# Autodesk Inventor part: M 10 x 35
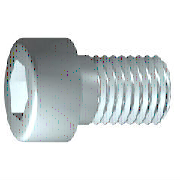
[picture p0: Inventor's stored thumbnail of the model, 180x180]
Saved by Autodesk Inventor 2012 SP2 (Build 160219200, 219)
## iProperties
IsCustomPart: 0
Created: 2009-02
Part Number: M 10 x 35
Material: 강, 연강
Description: 6각머리 태핑 나사
Document SubType Name: Modeling
Standard: KS B 1003
Designer: KYOUNG IL JANG
Standards Organization: KS
Language: ko-KR
Size Designation: M 10 x 35
Categories: <MemberInstance><Categories><Category DisplayName="조임쇠" InternalName="e4da775c-781d-43d5-af7c-5136215cf5a6" Mnemonic="FSTN"><Category DisplayName="볼트" InternalN
Density: 1 g/cm^3
Author: KYOUNG IL JANG
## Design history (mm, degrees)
workplane "Work Plane1"
fillet "Fillet2" dims "d30" = 0.1 (= R)
revolve "본체" stored, may be unused: angle "d10" = 90 deg
sketch "스케치2"
  geometry: L1 (0, -11.2)-(0, 11.2) reference; L2 (-11.2, 0)-(11.2, 0) reference; L3 (4.619, 0)-(2.309, -4); L4 (2.309, -4)-(-2.309, -4); L5 (-2.309, -4)-(-4.619, 0); L6 (-4.619, 0)-(-2.309, 4); L7 (-2.309, 4)-(2.309, 4); L8 (2.309, 4)-(4.619, 0); 2 further points
  constraints: 12 end point, 1 coincident, 1 horizontal alignment, 1 point on line, 12 other
extrude "슬롯" join sketch "스케치2" stored distance "d11" = 10; taper "d12" = 0 deg
body "Solid1"
fillet "모깎기1" dims "d17" = 1 (= RR)
feature "스레드" dims "d13" = 31.25 (= GEL), "d14" = 0
chamfer "모따기1" distance "d15" = 0.92018 (= -0.5 x SPD + 0.5 x GD); stored, may be unused: second distance "d16" = 0.92018 (= GUL), angle "d27" = 45 deg
sketch "스케치1"
  geometry: L1 (-2.333, 0)-(35, 0); L2 (35, 0)-(35, 5); L3 (35, 5)-(3.75, 5); L4 (3.75, 5)-(2.83, 5); L5 (2.83, 5)-(0, 5); L6 (0, 5)-(0, 8); L7 (0, 8)-(-10, 8); L8 (-10, 8)-(-10, 4.619); L9 (-10, 4.619)-(-5, 4.619); L10 (-5, 4.619)-(-2.333, 0); L11 (-19, 0)-(44, 0) reference; L12 (0, -1.6)-(0, 9.6) reference; L13 (3.75, 5)-(0, 5)
  constraints: 22 end point, 6 parallel, 2 collinear, 2 perpendicular, 1 horizontal, 1 point on line
  dimensions: "d1" = 31.25 distance from line of L3.end L2 (= GEL); "d2" = 0.92028 distance of L4.end L3.end (computed from GAL); "d3" = 10 distance between parallel lines of L8 L6 (= KOH); "d4" = 5 distance of L8.end L9.end (= INTI); "d5" = 60 deg angle of L10 L1; "d6" = 10 diameter of L3 L1 (= GD); "d7" = 10 diameter of L5 L1 (= BDM); "d8" = 9.2376 diameter of L9 L1 (= 1.1547 x SW); "d9" = 16 diameter of L7 L1 (= KOD); "d26" = 35 distance between parallel lines of L12 L2 (= NLG)
other parameters: "GD" = 10 (= NND) [user parameter; used in 2 equation terms], "NLG" = 35 [user parameter; used in 1 equation term], "GEL" = 31.25 [user parameter; used in 2 equation terms], "KOD" = 16 [user parameter; used in 1 equation term], "KOH" = 10 [user parameter; used in 1 equation term], "INTI" = 5 [user parameter; used in 1 equation term], "GAL" = 0.92018 (= 0.61345 x PTC) [user parameter; used in 1 equation term], "GUL" = 0.92018 (= 0.61345 x PTC) [user parameter; used in 1 equation term], "BDM" = 10 (= NND) [user parameter; used in 1 equation term], "SW" = 8 [user parameter; used in 2 equation terms], "RR" = 1 [user parameter; used in 1 equation term], "SPD" = 8.15965 (= NND - 1.2269 x PTC) [user parameter; used in 1 equation term], "d19" = 0, "d28" = 0, "d29" = 0, "R" = 0.1 [user parameter; used in 1 equation term], "PHH" = 0.4 [user parameter], "GD1" = 8.15965 (= THREADDIA - 1.2269 x PTC) [user parameter], "FAWI" = 45 deg [user parameter], "TPU" = 6.66667 (computed from PTC) [user parameter], "PTC" = 1.5 [user parameter; used in 5 equation terms], "TOA" = 30 deg [user parameter], "E0" = 9.24 (= 1.155 x SW) [user parameter]
